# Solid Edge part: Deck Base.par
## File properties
Username: m_hel
Author: m_hel
Template: Iso Metric Part.par
Last saved by: m_hel
Revision: 13
Application: Solid Edge
Accuracy: 0,990
Material: Textured White
Face Style: White painted
Fill Style: ANSI36(Marble)
Virtual Style: ANSI36(Marble)
Grouping: Uncategorized
LibraryName: Custom Materials
Coef. of Thermal Exp: 0.0
Thermal Conductivity: 0.0
Specific Heat: 0.0
Modulus of Elasticity: 0.0
Poisson's Ratio: 0.0
Yield Stress: 0.0
Ultimate Stress: 0.0
Elongation: 0.0
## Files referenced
..\Redfisher18.asm
G:\OneDriveTemp\OneDrive\Dokumendid\TLÜ tööd\3D Modelleerimine\3d modelling\veesõiduk\Deck1.par
G:\OneDriveTemp\OneDrive\Dokumendid\TLÜ tööd\3D Modelleerimine\3d modelling\veesõiduk\Hull.par
iduk\Deck1.par
iduk\Hull.par
iduk\Redfisher18.asm
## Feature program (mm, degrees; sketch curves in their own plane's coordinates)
sketch for "unnamed Protrusion 1" plane through (0, 0, 0) normal (0, 0, 1) x-axis (1, 0, 0)
  arc centre (2833.7179, -36.0362) radius 3868.5677 from (-960.2543, 720) to (-1034.8498, -36.0362) ccw
  line (-1034.8498, -36.0362) -> (-1034.8498, -1100)
  line (-1034.8498, -1100) -> (1034.8498, -1100)
  line (1034.8498, -36.0362) -> (1034.8498, -1100)
  arc centre (-2833.7179, -36.0362) radius 3868.5677 from (960.2543, 720) to (1034.8498, -36.0362) cw
  line (960.2543, 720) -> (-960.2543, 720)
extrude "unnamed Protrusion 1" add finite 400 along -normal
draft "Draft_1"  Angles1 = 10 deg
thinwall "Thinwall_1"  Thickness = 20 mm
fillet "Round_1" radius 30
sketch used by "ExtrudedProtrusion_2" plane through (0, -190, -400) normal (0, 0, 1) x-axis (0, -1, 0)
extrude "ExtrudedProtrusion_2" add finite 40 along +normal
sketch for "unnamed Cutout 1" plane through (0, -270, -360) normal (0, 0, 1) x-axis (0, -1, 0)
extrude "unnamed Cutout 1" cut through along -normal
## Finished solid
Body 1: solid body, 60 faces, 140 edges, 84 vertices.
  Faces by surface: cylinder 20, plane 20, sphere 8, blend 4, cone 4, torus 4
  Edges by curve: line 68, circle 56, intersection 12, ellipse 4
Bounding box of the edges (mm; curved faces can reach further): 2110.317 x 1860.000 x 420.000, from (-1055.1583, -1120, -420) to (1055.1583, 740, 0).
Cylindrical faces by radius (mm): R30 x16, R40 x4
Conical faces (half-angle, radius in mm at the cone's reference point): 10 deg R3868.5677 x2, 10 deg R3888.2638 x2
Toroidal faces (ring radius, tube radius in mm): R3772.8639 r30 x2, R3789.6459 r30 x2
Spherical faces by radius (mm): R30 x8
Planar faces by outward normal: +x 2, +y 4, +z 3, -x 2, -y 4, -z 1, oblique 4
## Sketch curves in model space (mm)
arc centre (-250, -520, -400) radius 40 from (-290, -520, -400) through (-277.4497, -549.0949, -400) to (-250, -560, -400)
line (-250, -560, -400) -> (250, -560, -400)
arc centre (250, -520, -400) radius 40 from (250, -560, -400) through (279.0949, -547.4497, -400) to (290, -520, -400)
line (290, -520, -400) -> (290, -20, -400)
arc centre (250, -20, -400) radius 40 from (290, -20, -400) through (277.4497, 9.0949, -400) to (250, 20, -400)
line (250, 20, -400) -> (-250, 20, -400)
arc centre (-250, -20, -400) radius 40 from (-290, -20, -400) through (-277.4497, 9.0949, -400) to (-250, 20, -400)
line (-290, -20, -400) -> (-290, -520, -400)
arc centre (2833.7179, -36.0362, 0) radius 3868.5677 from (-960.2543, 720, 0) through (-1016.1558, 343.8175, 0) to (-1034.8498, -36.0362, 0)
line (-1034.8498, -36.0362, 0) -> (-1034.8498, -1100, 0)
line (-1034.8498, -1100, 0) -> (1034.8498, -1100, 0)
line (1034.8498, -36.0362, 0) -> (1034.8498, -1100, 0)
arc centre (-2833.7179, -36.0362, 0) radius 3868.5677 from (960.2543, 720, 0) through (1016.1558, 343.8175, 0) to (1034.8498, -36.0362, 0)
line (960.2543, 720, 0) -> (-960.2543, 720, 0)
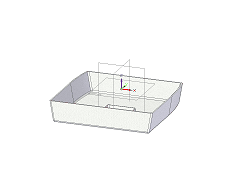
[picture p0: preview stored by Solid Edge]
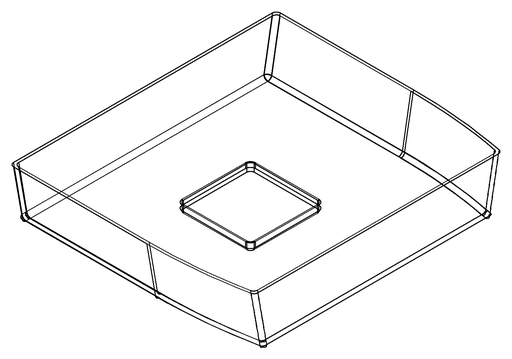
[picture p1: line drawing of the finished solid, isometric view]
